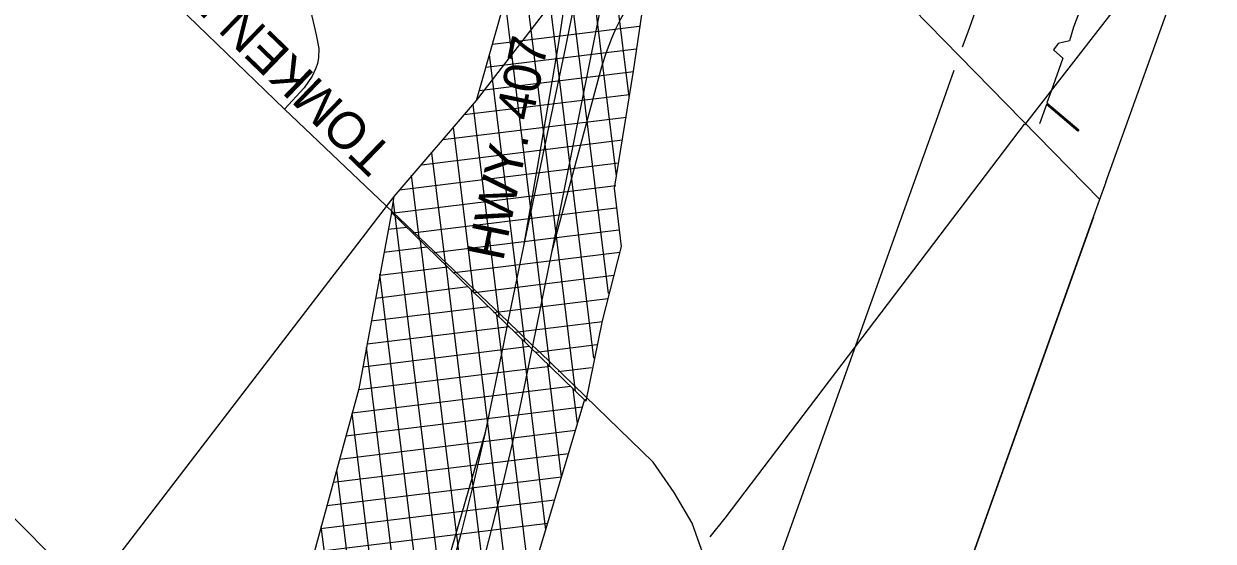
# Model space of a CAD drawing. Extents: x 586326 to 623965, y 4819854 to 4857850.
# Drawn here: x 604641 to 606246, y 4836952 to 4837651 of the extents above; entities that cross this region are included whole.
import ezdxf

# ---------------------------------------------------------------- set-up
doc = ezdxf.new("R2010")
doc.units = 0
for name, color, linetype in [('407 Parkway Belt', 7, 'Continuous'), ('Hydro ROW', 7, 'Continuous'), ('Lots_Concessions', 7, 'Continuous'), ('Major Rds and Hwys', 7, 'Continuous'), ('Major Rds Lbls', 7, 'Continuous'), ('Minor Rds', 7, 'Continuous'), ('Municipal Bdry', 7, 'Continuous')]:
    doc.layers.add(name, color=color, linetype=linetype)

msp = doc.modelspace()

# ---------------------------------------------------------------- linework, layer by layer
at = {"layer": '407 Parkway Belt'}
for p, q in [((605457.8, 4837552.2), (605388.5, 4838117.2)), ((605440.8, 4837445.1), (605375, 4837980.9)), ((605430, 4837286.6), (605353.7, 4837907.7)), ((605410.5, 4837199.4), (605332.8, 4837832.2)), ((605385.7, 4837154.7), (605311.6, 4837758.4)), ((605351.1, 4837190.7), (605290.5, 4837684.1)), ((605471.3, 4837647.4), (605273.4, 4837623.1)), ((605467.5, 4837616.7), (605264.4, 4837591.8)), ((605317.1, 4837221.4), (605269.5, 4837609.4)), ((605464, 4837586.1), (605255.7, 4837560.5)), ((605457.9, 4837555.1), (605235.3, 4837527.8)), ((605282.7, 4837255.5), (605247.5, 4837542)), ((605454.3, 4837524.4), (605206.5, 4837494)), ((605248.6, 4837287.2), (605221.1, 4837511.4)), ((605449.1, 4837493.6), (605177.7, 4837460.2)), ((605210.6, 4837324), (605191.8, 4837476.8)), ((605443.8, 4837462.7), (605148, 4837426.4)), ((605175.2, 4837358.5), (605164.4, 4837446.4)), ((605439.9, 4837432), (605137.2, 4837394.8)), ((605272.4, 4836331.6), (605139.9, 4837410.7)), ((605440.1, 4837401.8), (605165.5, 4837368.1)), ((605157.9, 4837376), (605132.9, 4837372.9)), ((605444.1, 4837372.1), (605194.7, 4837341.4)), ((605185.5, 4837349.2), (605127.2, 4837342)), ((605263.7, 4836649), (605176.6, 4837357.8)), ((605445.2, 4837342), (605222.1, 4837314.6)), ((605213.1, 4837322.3), (605121.5, 4837311.1)), ((605283.7, 4836732.3), (605211, 4837324.4)), ((605238.8, 4836359.3), (605121.7, 4837312.6)), ((605437.4, 4837310.8), (605248.7, 4837287.6)), ((605240.8, 4837295.5), (605115.8, 4837280.1)), ((605303.7, 4836815.5), (605245.3, 4837291.1)), ((605268.4, 4837268.7), (605110.1, 4837249.2)), ((605429.1, 4837279.5), (605275, 4837260.6)), ((605324.1, 4836895.4), (605279.6, 4837257.7)), ((605296, 4837241.8), (605104.4, 4837218.3)), ((605422, 4837248.4), (605304.4, 4837234)), ((605345.5, 4836967.4), (605313.9, 4837224.4)), ((605323.6, 4837215), (605098.7, 4837187.4)), ((605204.6, 4836391.6), (605103.6, 4837214.2)), ((605329, 4837206.8), (605328.9, 4837206.8)), ((605414.3, 4837217.3), (605332.3, 4837207.2)), ((605351.2, 4837188.2), (605092.8, 4837156.4)), ((605366.9, 4837039.3), (605348.2, 4837191.1)), ((605407.1, 4837186.2), (605362.3, 4837180.7)), ((605378.8, 4837161.3), (605084.3, 4837125.2)), ((605388.3, 4837111.2), (605382.6, 4837157.7)), ((605394.8, 4837133), (605075.8, 4837093.9)), ((605172, 4836411.3), (605084.3, 4837125.1)), ((605385.4, 4837101.7), (605067.3, 4837062.6)), ((605376.1, 4837070.3), (605058.7, 4837031.3)), ((605155.3, 4836301.1), (605063.5, 4837048.7)), ((605366.8, 4837038.9), (605050.2, 4837000.1)), ((605357.4, 4837007.6), (605041.7, 4836968.8)), ((605348.1, 4836976.2), (605033.2, 4836937.5)), ((605138.6, 4836190.9), (605042.6, 4836972.2))]:
    msp.add_line(p, q, dxfattribs=at)
msp.add_lwpolyline([(605137.2, 4837396.1), (605140.9, 4837417.5), (605251.8, 4837547.3), (605383.6, 4838012.6), (605353.9, 4838056.8), (605363.6, 4838074.9), (605232.9, 4838235.1), (605246.6, 4838253.5), (605785.1, 4837716.2), (605767.9, 4837696.3), (605534.2, 4837878.2), (605490.5, 4837770.2), (605463.4, 4837587), (605437.9, 4837428.9), (605447.4, 4837350.3), (605421.4, 4837250), (605399.5, 4837141.3)], close=True, dxfattribs=at)
msp.add_lwpolyline([(605317.9, 4836874.7), (605398.1, 4837144.1), (605399.5, 4837141.3), (605137.2, 4837396.1), (605093.2, 4837157.8), (605032.2, 4836933.9)], dxfattribs=at)
at = {"layer": 'Hydro ROW'}
for p, q in [((606156.8, 4838317), (605914.7, 4837639.6)), ((606077.3, 4837698.4), (606057.5, 4837646.2)), ((605914.7, 4837639.6), (605907.4, 4837619.2)), ((606057.5, 4837646.2), (606052.3, 4837627.7)), ((606036.8, 4837624.1), (606030.3, 4837615.7)), ((606052.3, 4837627.7), (606036.8, 4837624.1)), ((606043.1, 4837604.6), (606027.4, 4837560.1)), ((606030.3, 4837615.7), (606043.1, 4837604.6)), ((605896.1, 4837587.6), (605888.4, 4837566.1)), ((605888.4, 4837566.1), (605873.8, 4837525.2)), ((606027.4, 4837560.1), (606021.6, 4837544)), ((606020.9, 4837541.9), (606011.6, 4837515.8)), ((606063.5, 4837506.1), (606020.9, 4837541.9)), ((606021.6, 4837544), (606064.8, 4837507.7)), ((605873.8, 4837525.2), (605823.6, 4837384.7)), ((606064.8, 4837507.7), (606063.5, 4837506.1)), ((605823.6, 4837384.7), (605661.2, 4836930)), ((606084.3, 4837389.9), (605844.4, 4836718.4))]:
    msp.add_line(p, q, dxfattribs=at)
at = {"layer": 'Lots_Concessions'}
for p, q in [((605251.8, 4837547.3), (605544.3, 4837926)), ((606023.4, 4837555.1), (606246, 4837842.1)), ((605991.9, 4837514.4), (606023.4, 4837555.1)), ((605140.9, 4837417.5), (605251.8, 4837547.3)), ((605587.4, 4836983.4), (605991.4, 4837515.4)), ((605118.5, 4837388.3), (605140.9, 4837417.5)), ((605075.8, 4837332.7), (605118.5, 4837388.3)), ((605057.3, 4837308.6), (605075.8, 4837332.7)), ((604735.8, 4836889.8), (605057.3, 4837308.6)), ((605567.3, 4836958.3), (605587.4, 4836983.4))]:
    msp.add_line(p, q, dxfattribs=at)
at = {"layer": 'Major Rds and Hwys'}
for points in [[(605334.8, 4838137.3), (605343.8, 4838126.8), (605355.6, 4838112.7), (605363.8, 4838101.3), (605371.9, 4838088.9), (605379.6, 4838075.2), (605385.8, 4838062.8), (605391.9, 4838048.7), (605396.6, 4838034.4), (605401.1, 4838019.8), (605404.1, 4838005.9), (605406.1, 4837993.7), (605407.3, 4837982.3), (605407.9, 4837970.9), (605408.3, 4837958.4), (605408.2, 4837946.9), (605407.7, 4837934.9), (605406.7, 4837922.3), (605405.4, 4837910.8), (605362.5, 4837625.3), (605335.6, 4837467.4), (605315.4, 4837350.7)], [(605354.3, 4837344.4), (605413.7, 4837643.7), (605422.9, 4837688.8), (605432.7, 4837733.9), (605448.4, 4837799.4), (605465.3, 4837864.9), (605484, 4837930.2), (605504.2, 4837998)], [(605445.9, 4837934.2), (605432.8, 4837887.4), (605420.9, 4837839.7), (605409, 4837792.8), (605398, 4837745.4), (605384.8, 4837682.2), (605372.3, 4837619.9), (605315.4, 4837350.7)], [(605354.3, 4837344.4), (605421.3, 4837593.4), (605427.3, 4837612.4), (605434.5, 4837631.4), (605439.8, 4837643.9), (605446.9, 4837657.8), (605455.1, 4837672.4), (605464.4, 4837685.8), (605474.3, 4837699.4), (605486, 4837712.7), (605636.5, 4837866.6)], [(604992.9, 4837535.4), (604784.2, 4837737.7), (604701, 4837822.2)], [(606092.8, 4837413.6), (605819.6, 4837693.8)], [(605294.5, 4837248.7), (604992.9, 4837535.4)], [(605315.4, 4837350.7), (605294.5, 4837248.7)], [(605328.2, 4837216.1), (605354.3, 4837344.4)], [(605294.5, 4837248.7), (605288.6, 4837218.8), (605263.5, 4837099)], [(605328.2, 4837216.1), (605310.5, 4837233.2), (605294.5, 4837248.7)], [(605221, 4836783.9), (605243.3, 4836858.8), (605263.9, 4836933.8), (605283, 4837009.4), (605300.9, 4837086), (605318.5, 4837169.5), (605328.2, 4837216.1)], [(605424, 4836234.3), (605415.5, 4836270.7), (605410.3, 4836308.6), (605410.4, 4836355.8), (605417, 4836400), (605424.9, 4836432.6), (605436.2, 4836468.4), (605531.3, 4836713.3), (605544.5, 4836750.7), (605556.7, 4836787.8), (605563.5, 4836828.4), (605565.5, 4836883.4), (605557.9, 4836934.5), (605543.1, 4836976.5), (605518.9, 4837018.2), (605490.6, 4837058.9), (605337.5, 4837207.4), (605328.2, 4837216.1)], [(605263.5, 4837099), (605247.5, 4837028.9), (605230.5, 4836960.2), (605211.5, 4836892), (605191.8, 4836823.7), (605170.2, 4836756.3), (605147.1, 4836687.7), (605122.6, 4836621.5), (605097.1, 4836555.5), (605083.6, 4836522), (605078.4, 4836508.9), (605059.3, 4836463.2), (605049.2, 4836440.6), (605039.1, 4836417.9), (605018.9, 4836373.3), (604997.6, 4836328.3), (604976, 4836284.3), (604953.3, 4836239.8), (604930.2, 4836195.7), (604896, 4836134.9), (604861.7, 4836073.9), (604838.9, 4836034)], [(605263.5, 4837099), (605213.7, 4836926.4), (605198.8, 4836883.8), (605182.7, 4836843), (605166, 4836801.2), (605147.9, 4836760.2), (605128.7, 4836715.4), (605113.5, 4836681)]]:
    msp.add_lwpolyline(points, dxfattribs=at)
at = {"layer": 'Minor Rds'}
for points in [[(605141.1, 4837896.8), (605033.7, 4837755.2), (605028.5, 4837746.5), (605024.4, 4837736.3), (605021.4, 4837723.3), (605020.4, 4837711.9), (605021.5, 4837700.2), (605027.1, 4837673.1), (605035.6, 4837635.9), (605039.1, 4837617.7), (605038.9, 4837604.8), (605037.4, 4837597.2), (605035.4, 4837591), (605030.1, 4837580.3), (605019.7, 4837564.6), (604992.9, 4837535.4)], [(604935.4, 4836690.8), (604919.9, 4836695.5), (604917, 4836697.2), (604901.4, 4836710.1), (604803.3, 4836807.4), (604414.2, 4837198.2), (604403.2, 4837211.9), (604394.6, 4837226), (604388.2, 4837239.4), (604383.2, 4837254.3), (604379.8, 4837269.1)]]:
    msp.add_lwpolyline(points, dxfattribs=at)
at = {"layer": 'Municipal Bdry'}
for p, q in [((606101.2, 4837437.1), (606246, 4837842.1)), ((606087.2, 4837397.9), (606101.4, 4837437.5)), ((605844.4, 4836718.4), (606087.2, 4837397.9))]:
    msp.add_line(p, q, dxfattribs=at)

# ---------------------------------------------------------------- texts
at = {"layer": 'Major Rds Lbls'}
for s, rotation, p in [('TOMKEN RD', 136.0004, (605142.1, 4837478.7)), ('HWY. 407', 78.2907, (605287.8, 4837329.1))]:
    msp.add_text(s, height=49.99, rotation=rotation, dxfattribs=at).set_placement(p)

doc.saveas('drawing.dxf')
